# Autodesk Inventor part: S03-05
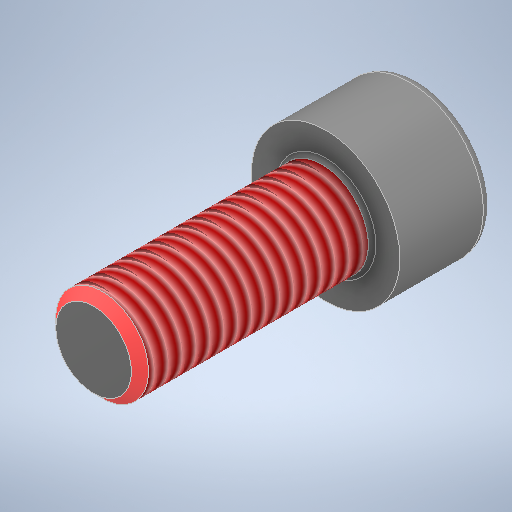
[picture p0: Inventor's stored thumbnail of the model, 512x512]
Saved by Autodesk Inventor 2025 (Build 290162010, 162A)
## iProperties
Manager: ISO 4762 (DIN 912)
Created: 2025-04
Part Number: S03-05
Material: Všeobecné
Document SubType Name: Modeling
Designer: Patrik
Density: 1 g/cm^3
Appearance: Výchozí
Description: Imbusový šroub s válcovou hlavou
Stock Number: E 1200/10x25
Mass: 3.67525 g
Surface Area: 17.8338 cm^2
Volume: 3.67525 cm^3
User Status: 12.9
Author: Patrik
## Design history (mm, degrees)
feature "Base1"
feature "Závit1" dims "d0" = 23.68, "d1" = 0
node "Těleso1"
